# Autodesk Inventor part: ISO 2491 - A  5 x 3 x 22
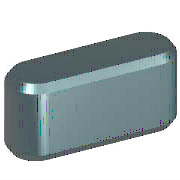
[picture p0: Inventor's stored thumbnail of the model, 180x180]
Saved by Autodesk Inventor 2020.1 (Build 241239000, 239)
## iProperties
Created: 2019-01
Part Number: ISO 2491 - A  5 x 3 x 22
Material: Stahl, weich
Description: Passfedern
Document SubType Name: Modeling
Standard: ISO 2491
Designer: lutzd
Standard Revision: First edition 1974-08-15
Standards Organization: ISO
Language: de-DE
Size Designation: A  5 x 3 x 22
Categories: <MemberInstance><Categories><Category DisplayName="Wellenteile" InternalName="7f7aeb1f-a693-4053-b835-cee3144e0d98" Mnemonic="SHFT"><Category DisplayName="Passf
Mass: 2.40277 g
Surface Area: 3.34683 cm^2
Volume: 0.306086 cm^3
Density: 7.85 g/cm^3
Appearance: Halbpoliert
IsCustomPart: 0
Author: lutzd
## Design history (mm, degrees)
workplane "Work Plane1"
workplane "Work Plane2"
sketch "Skizze1"
  geometry: L1 (2.5, 2.5)-(19.5, 2.5); L2 (19.5, -2.5)-(2.5, -2.5); L3 (0, 9.4)-(0, -7.4) reference; L4 (-5, 0)-(30, 0) reference; L5 (22, 0)-(22, 7); A1 r 2.5 centre (2.5, 0) between (2.5, 2.5) and (2.5, -2.5); A2 r 2.5 centre (19.5, 0) between (19.5, -2.5) and (19.5, 2.5)
  constraints: 6 end point, 5 point on circle, 4 tangent, 3 point on line, 2 centre point, 1 horizontal, 1 parallel, 1 perpendicular
  dimensions: "d0" = 2.5 radius of A1 (= 0.5 x PB); "d13" = 2.5 radius of A2 (= 0.5 x PB); "d14" = 22 distance between parallel lines of L5 L3 (= NLG)
extrude "Körper1" new body sketch "Skizze1" taper "d3" = 0 deg; stored distance "d4" = 10
workplane "Work Plane3"
body "Solid1"
chamfer "Fase1" distance "d8" = 0.4 (= PHH); stored, may be unused: second distance "d9" = 0.4 (= PHH), angle "d15" = 45 deg
other parameters: "d1" = -1.8 (= -PNT), "d2" = 1.2 (= PH - PNT), "NLG" = 22 [user parameter; used in 1 equation term], "PB" = 5 [user parameter; used in 2 equation terms], "PNT" = 1.8 [user parameter; used in 2 equation terms], "PH" = 3 [user parameter; used in 1 equation term], "PHH" = 0.4 [user parameter; used in 2 equation terms], "d10" = 0, "d16" = 0, "d17" = 0, "d18" = 0, "RR" = 0.16 [user parameter], "WDMIN" = 12 [user parameter], "WDMAX" = 17 [user parameter], "PLB1" = 22 [user parameter], "PLB2" = 22 [user parameter], "PUEB" = 1.4 [user parameter]
